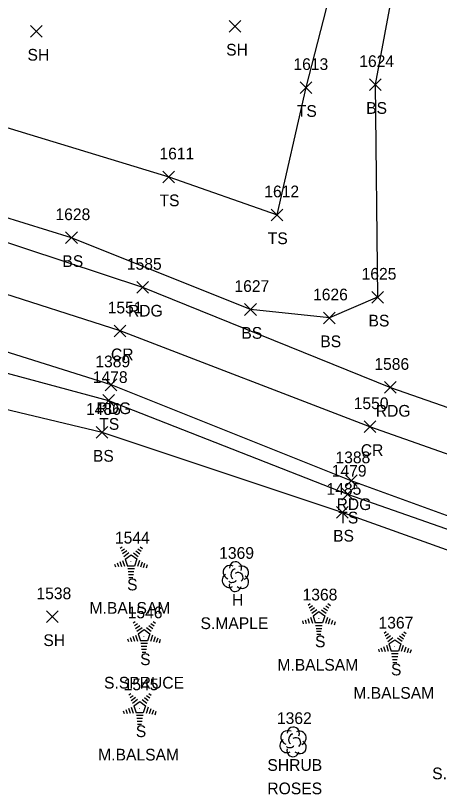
# Model space of a CAD drawing. Extents: x 1609623 to 1616187, y 756677 to 762826.
# Drawn here: x 1610422.7 to 1610495.1, y 761636.2 to 761769.2 of the extents above; entities that cross this region are included whole.
import ezdxf

# ---------------------------------------------------------------- set-up
doc = ezdxf.new("R2010")
doc.units = 0
for name, color, linetype in [('L_A', 7, 'Continuous'), ('L_C', 7, 'Continuous'), ('L_I', 7, 'Continuous'), ('L_TIC', 7, 'Continuous'), ('LELB', 7, 'Continuous'), ('LSH', 7, 'Continuous'), ('LTC', 7, 'Continuous'), ('LTD', 7, 'Continuous'), ('P_A', 7, 'Continuous'), ('P_I', 7, 'Continuous'), ('P_TIC', 7, 'Continuous'), ('PEU', 7, 'Continuous'), ('PRC', 7, 'Continuous')]:
    doc.layers.add(name, color=color, linetype=linetype)

msp = doc.modelspace()

# ---------------------------------------------------------------- linework, layer by layer
at = {"layer": 'L_TIC'}
for points in [[(1610459.18, 761766.38), (1610461.18, 761768.38)], [(1610461.18, 761766.38), (1610459.18, 761768.38)], [(1610425.22, 761765.51), (1610427.22, 761767.51)], [(1610427.22, 761765.51), (1610425.22, 761767.51)], [(1610471.33, 761755.91), (1610473.33, 761757.91)], [(1610473.33, 761755.91), (1610471.33, 761757.91)], [(1610483.15, 761756.42), (1610485.15, 761758.42)], [(1610485.15, 761756.42), (1610483.15, 761758.42)], [(1610447.86, 761740.64), (1610449.86, 761742.64)], [(1610449.86, 761740.64), (1610447.86, 761742.64)], [(1610466.36, 761734.16), (1610468.36, 761736.16)], [(1610468.36, 761734.16), (1610466.36, 761736.16)], [(1610431.23, 761730.26), (1610433.23, 761732.26)], [(1610433.23, 761730.26), (1610431.23, 761732.26)], [(1610483.55, 761720.1), (1610485.55, 761722.1)], [(1610485.55, 761720.1), (1610483.55, 761722.1)], [(1610461.82, 761718), (1610463.82, 761720)], [(1610463.82, 761718), (1610461.82, 761720)], [(1610475.31, 761716.56), (1610477.31, 761718.56)], [(1610477.31, 761716.56), (1610475.31, 761718.56)], [(1610437.56, 761702.45), (1610439.56, 761704.45)], [(1610439.56, 761702.45), (1610437.56, 761704.45)], [(1610436.45, 761697), (1610438.45, 761699)], [(1610438.45, 761697), (1610436.45, 761699)], [(1610478.41, 761686.45), (1610480.41, 761688.45)], [(1610480.41, 761686.45), (1610478.41, 761688.45)], [(1610477.5, 761683.35), (1610479.5, 761685.35)], [(1610479.5, 761683.35), (1610477.5, 761685.35)], [(1610427.93, 761665.51), (1610429.93, 761667.51)], [(1610429.93, 761665.51), (1610427.93, 761667.51)]]:
    msp.add_lwpolyline(points, dxfattribs=at)
at = {"layer": 'LELB'}
for points in [[(1610493.54, 761807.83), (1610484.15, 761757.42), (1610484.55, 761721.1), (1610476.31, 761717.56), (1610462.82, 761719), (1610432.23, 761731.26), (1610407.92, 761738.73), (1610372.44, 761750.91), (1610345.83, 761758.18), (1610340.75, 761759.13), (1610336.33, 761759.9), (1610330.48, 761773.16), (1610321.56, 761783.18), (1610327.07, 761799.85), (1610336.71, 761810.65), (1610352.98, 761818.88), (1610362.46, 761822.54)], [(1610419.05, 761750.7), (1610448.86, 761741.64), (1610467.36, 761735.16), (1610472.33, 761756.91), (1610479.31, 761783.98), (1610481.94, 761811.25), (1610453.47, 761810.17), (1610420.45, 761799.24), (1610406.2, 761793.3), (1610384.28, 761797.2), (1610367.96, 761799.15), (1610357.1, 761783.9)], [(1610257.48, 761736.51), (1610289.65, 761735.58), (1610333.79, 761730.74), (1610390.78, 761716.31), (1610438.56, 761703.45), (1610479.41, 761687.45), (1610522.96, 761672.19), (1610559.63, 761661.11), (1610576.64, 761653.22)], [(1610558.74, 761658.14), (1610522.76, 761668.49), (1610478.5, 761684.35), (1610437.45, 761698), (1610388.31, 761709.71), (1610348.03, 761719.28), (1610335.94, 761728.39)]]:
    msp.add_lwpolyline(points, dxfattribs=at)
at = {"layer": 'LSH'}
msp.add_line((1610470.08, 761645.19), (1610470.08, 761645.19), dxfattribs=at)
msp.add_line((1610470.08, 761645.19), (1610470.08, 761645.19), dxfattribs=at)
msp.add_arc((1610470.13, 761646.63), 1.05, 335.5272, 180.9563, dxfattribs=at)
for centre, major_axis, ratio, start_param, end_param in [((1610469.29, 761645.86), (1.21, -0.51), 0.895232, 1.570796, 4.712389), ((1610471.12, 761645.78), (-1.14, -0.48), 0.949671, 1.570796, 4.712389), ((1610469.87, 761645.65), (-0.208, -0.792), 0.645439, 3.141593, 6.283185), ((1610470.58, 761645.03), (-0.5, 0.667), 0.989748, 3.141593, 6.283185), ((1610469, 761644.48), (0.58, -1.04), 0.959034, 3.141593, 6.283185), ((1610469.62, 761644.44), (-0.625, -0.083), 0.423636, 0, 3.141593), ((1610471.08, 761644.36), (-1.09, 0.79), 0.841452, 1.570796, 4.712389), ((1610470.08, 761643.69), (0.26, 1.06), 0.942809, 1.570796, 4.712389)]:
    msp.add_ellipse(centre, major_axis=major_axis, ratio=ratio, start_param=start_param, end_param=end_param, dxfattribs=at)
at = {"layer": 'LTC'}
for p, q in [((1610440.54, 761678.23), (1610440.9, 761678.48)), ((1610440.75, 761677.76), (1610441.28, 761678.14)), ((1610440.96, 761677.29), (1610441.66, 761677.81)), ((1610443.2, 761677.77), (1610443.88, 761677.28)), ((1610443.57, 761678.12), (1610444.12, 761677.72)), ((1610443.94, 761678.47), (1610444.36, 761678.16)), ((1610441.17, 761676.83), (1610442.05, 761677.47)), ((1610441.39, 761676.37), (1610442.41, 761677.11)), ((1610441.39, 761676.37), (1610441.78, 761675.18)), ((1610442.41, 761677.11), (1610443.4, 761676.38)), ((1610442.83, 761677.42), (1610443.64, 761676.83)), ((1610443.4, 761676.38), (1610443.01, 761675.18)), ((1610439.57, 761675.5), (1610439.73, 761675.04)), ((1610440.03, 761675.72), (1610440.24, 761675.07)), ((1610440.48, 761675.94), (1610440.76, 761675.1)), ((1610440.94, 761676.15), (1610441.27, 761675.14)), ((1610443.01, 761675.18), (1610441.78, 761675.18)), ((1610443.84, 761676.11), (1610443.5, 761675.07)), ((1610444.29, 761675.86), (1610444, 761674.98)), ((1610444.73, 761675.61), (1610444.49, 761674.88)), ((1610445.17, 761675.36), (1610444.99, 761674.79)), ((1610442.97, 761674.68), (1610441.83, 761674.68)), ((1610442.89, 761674.18), (1610441.9, 761674.18)), ((1610442.81, 761673.68), (1610441.97, 761673.68)), ((1610442.72, 761673.18), (1610442.05, 761673.18)), ((1610472.66, 761668.51), (1610473.01, 761668.77)), ((1610472.87, 761668.05), (1610473.4, 761668.43)), ((1610475.68, 761668.4), (1610476.23, 761668.01)), ((1610476.05, 761668.75), (1610476.47, 761668.45)), ((1610473.08, 761667.58), (1610473.78, 761668.09)), ((1610473.29, 761667.12), (1610474.16, 761667.75)), ((1610473.51, 761666.66), (1610474.52, 761667.4)), ((1610474.52, 761667.4), (1610475.52, 761666.67)), ((1610474.94, 761667.71), (1610475.75, 761667.12)), ((1610475.31, 761668.06), (1610475.99, 761667.56)), ((1610442.77, 761665.46), (1610443.12, 761665.72)), ((1610446.17, 761665.7), (1610446.59, 761665.4)), ((1610471.69, 761665.79), (1610471.84, 761665.32)), ((1610472.14, 761666.01), (1610472.36, 761665.36)), ((1610472.6, 761666.23), (1610472.87, 761665.39)), ((1610473.06, 761666.44), (1610473.39, 761665.42)), ((1610473.51, 761666.66), (1610473.9, 761665.47)), ((1610475.52, 761666.67), (1610475.13, 761665.47)), ((1610475.96, 761666.4), (1610475.62, 761665.36)), ((1610476.4, 761666.15), (1610476.11, 761665.26)), ((1610476.85, 761665.9), (1610476.61, 761665.17)), ((1610477.29, 761665.65), (1610477.1, 761665.07)), ((1610442.98, 761665), (1610443.51, 761665.38)), ((1610443.19, 761664.53), (1610443.89, 761665.04)), ((1610443.4, 761664.07), (1610444.28, 761664.7)), ((1610443.62, 761663.61), (1610444.63, 761664.35)), ((1610444.63, 761664.35), (1610445.63, 761663.62)), ((1610445.05, 761664.66), (1610445.86, 761664.07)), ((1610445.43, 761665.01), (1610446.11, 761664.51)), ((1610445.8, 761665.35), (1610446.35, 761664.96)), ((1610475.13, 761665.47), (1610473.9, 761665.47)), ((1610475.09, 761664.97), (1610473.94, 761664.97)), ((1610475.01, 761664.47), (1610474.02, 761664.47)), ((1610442.26, 761662.96), (1610442.47, 761662.31)), ((1610442.71, 761663.18), (1610442.98, 761662.34)), ((1610443.17, 761663.39), (1610443.5, 761662.37)), ((1610443.62, 761663.61), (1610444.01, 761662.42)), ((1610445.63, 761663.62), (1610445.24, 761662.42)), ((1610446.07, 761663.35), (1610445.73, 761662.31)), ((1610446.51, 761663.1), (1610446.23, 761662.21)), ((1610474.92, 761663.97), (1610474.09, 761663.97)), ((1610474.84, 761663.47), (1610474.16, 761663.47)), ((1610485.64, 761663.71), (1610485.99, 761663.97)), ((1610485.85, 761663.24), (1610486.38, 761663.63)), ((1610486.06, 761662.78), (1610486.76, 761663.29)), ((1610488.29, 761663.25), (1610488.97, 761662.76)), ((1610488.66, 761663.6), (1610489.21, 761663.2)), ((1610489.03, 761663.95), (1610489.45, 761663.64)), ((1610441.8, 761662.74), (1610441.95, 761662.27)), ((1610445.24, 761662.42), (1610444.01, 761662.42)), ((1610445.2, 761661.92), (1610444.06, 761661.92)), ((1610446.96, 761662.85), (1610446.72, 761662.12)), ((1610447.4, 761662.6), (1610447.22, 761662.02)), ((1610486.04, 761661.64), (1610486.37, 761660.62)), ((1610486.27, 761662.31), (1610487.14, 761662.95)), ((1610486.49, 761661.86), (1610487.5, 761662.59)), ((1610486.49, 761661.86), (1610486.88, 761660.66)), ((1610487.5, 761662.59), (1610488.5, 761661.87)), ((1610487.92, 761662.9), (1610488.73, 761662.32)), ((1610488.5, 761661.87), (1610488.11, 761660.66)), ((1610445.12, 761661.42), (1610444.13, 761661.42)), ((1610445.03, 761660.92), (1610444.2, 761660.92)), ((1610444.95, 761660.42), (1610444.28, 761660.42)), ((1610484.67, 761660.99), (1610484.82, 761660.52)), ((1610485.12, 761661.2), (1610485.34, 761660.55)), ((1610485.58, 761661.42), (1610485.85, 761660.59)), ((1610488.11, 761660.66), (1610486.88, 761660.66)), ((1610488.94, 761661.6), (1610488.6, 761660.56)), ((1610489.38, 761661.34), (1610489.09, 761660.46)), ((1610489.83, 761661.09), (1610489.59, 761660.37)), ((1610490.27, 761660.84), (1610490.08, 761660.27)), ((1610488.07, 761660.16), (1610486.92, 761660.16)), ((1610487.99, 761659.66), (1610487, 761659.66)), ((1610487.9, 761659.16), (1610487.07, 761659.16)), ((1610487.82, 761658.66), (1610487.14, 761658.66)), ((1610442.03, 761653.17), (1610442.38, 761653.42)), ((1610442.24, 761652.7), (1610442.77, 761653.08)), ((1610442.45, 761652.23), (1610443.15, 761652.75)), ((1610442.66, 761651.77), (1610443.53, 761652.41)), ((1610444.31, 761652.36), (1610445.12, 761651.77)), ((1610444.68, 761652.71), (1610445.36, 761652.22)), ((1610445.05, 761653.06), (1610445.6, 761652.66)), ((1610445.43, 761653.41), (1610445.84, 761653.1)), ((1610442.43, 761651.09), (1610442.76, 761650.07)), ((1610442.88, 761651.31), (1610443.89, 761652.05)), ((1610442.88, 761651.31), (1610443.27, 761650.12)), ((1610443.89, 761652.05), (1610444.89, 761651.32)), ((1610444.89, 761651.32), (1610444.5, 761650.12)), ((1610445.33, 761651.05), (1610444.99, 761650.01)), ((1610441.06, 761650.44), (1610441.21, 761649.98)), ((1610441.52, 761650.66), (1610441.73, 761650.01)), ((1610441.97, 761650.88), (1610442.24, 761650.04)), ((1610444.5, 761650.12), (1610443.27, 761650.12)), ((1610445.77, 761650.8), (1610445.48, 761649.92)), ((1610446.22, 761650.55), (1610445.98, 761649.82)), ((1610446.66, 761650.3), (1610446.47, 761649.73)), ((1610444.46, 761649.62), (1610443.32, 761649.62)), ((1610444.38, 761649.12), (1610443.39, 761649.12)), ((1610444.29, 761648.62), (1610443.46, 761648.62)), ((1610444.21, 761648.12), (1610443.53, 761648.12))]:
    msp.add_line(p, q, dxfattribs=at)
at = {"layer": 'LTD'}
msp.add_line((1610460.22, 761673.41), (1610460.22, 761673.41), dxfattribs=at)
msp.add_line((1610460.22, 761673.41), (1610460.22, 761673.41), dxfattribs=at)
msp.add_arc((1610460.27, 761674.84), 1.05, 335.5272, 180.9563, dxfattribs=at)
for centre, major_axis, ratio, start_param, end_param in [((1610459.43, 761674.07), (1.21, -0.51), 0.895232, 1.570796, 4.712389), ((1610461.26, 761673.99), (-1.14, -0.48), 0.949671, 1.570796, 4.712389), ((1610459.14, 761672.7), (0.58, -1.04), 0.959034, 3.141593, 6.283185), ((1610460.01, 761673.86), (-0.208, -0.792), 0.645439, 3.141593, 6.283185), ((1610460.72, 761673.24), (-0.5, 0.667), 0.989748, 3.141593, 6.283185), ((1610459.76, 761672.66), (-0.625, -0.083), 0.423636, 0, 3.141593), ((1610461.22, 761672.57), (-1.09, 0.79), 0.841452, 1.570796, 4.712389), ((1610460.22, 761671.91), (0.26, 1.06), 0.942809, 1.570796, 4.712389)]:
    msp.add_ellipse(centre, major_axis=major_axis, ratio=ratio, start_param=start_param, end_param=end_param, dxfattribs=at)
at = {"layer": 'P_TIC'}
for points in [[(1610443.38, 761721.79), (1610445.38, 761723.79)], [(1610445.38, 761721.79), (1610443.38, 761723.79)], [(1610439.53, 761714.33), (1610441.53, 761716.33)], [(1610441.53, 761714.33), (1610439.53, 761716.33)], [(1610438, 761705.13), (1610440, 761707.13)], [(1610440, 761705.13), (1610438, 761707.13)], [(1610485.74, 761704.69), (1610487.74, 761706.69)], [(1610487.74, 761704.69), (1610485.74, 761706.69)], [(1610482.24, 761697.98), (1610484.24, 761699.98)], [(1610484.24, 761697.98), (1610482.24, 761699.98)], [(1610479.04, 761688.74), (1610481.04, 761690.74)], [(1610481.04, 761688.74), (1610479.04, 761690.74)]]:
    msp.add_lwpolyline(points, dxfattribs=at)
at = {"layer": 'PEU'}
for points in [[(1610292.65, 761756.84), (1610337.52, 761752.5), (1610397.05, 761738.41), (1610444.38, 761722.79), (1610486.74, 761705.69), (1610529.9, 761690.62)], [(1610523.28, 761673.99), (1610480.04, 761689.74), (1610439, 761706.13), (1610392.08, 761720.87), (1610334.48, 761734.06), (1610288.63, 761739.63), (1610237.75, 761740.33), (1610189.36, 761741.54), (1610151.21, 761743.29), (1610095.63, 761747.13), (1610049.42, 761749.13), (1609994.68, 761742.82), (1609943, 761732.03), (1609889.61, 761718.43), (1609806.51, 761697.21)]]:
    msp.add_lwpolyline(points, dxfattribs=at)
at = {"layer": 'PRC'}
msp.add_lwpolyline([(1610601.8, 761670.75), (1610582.15, 761672.46), (1610527.05, 761683.5), (1610483.24, 761698.98), (1610440.53, 761715.33), (1610395.01, 761729.94), (1610335.18, 761743.5), (1610288.69, 761747.54), (1610237.99, 761746.29), (1610189.61, 761747.71), (1610150.7, 761750.53), (1610096.59, 761755.33), (1610048.73, 761756.09), (1609993.41, 761750.2), (1609941.26, 761738.94), (1609887.62, 761725.82), (1609805.01, 761705.08)], dxfattribs=at)

# ---------------------------------------------------------------- texts
at = {"layer": 'L_A'}
for s, p in [('SH', (1610458.66, 761762.38)), ('SH', (1610424.71, 761761.51)), ('TS', (1610470.74, 761751.91)), ('BS', (1610482.59, 761752.42)), ('TS', (1610447.27, 761736.64)), ('TS', (1610465.77, 761730.16)), ('BS', (1610430.67, 761726.26)), ('BS', (1610482.99, 761716.1)), ('BS', (1610461.26, 761714)), ('BS', (1610474.75, 761712.56)), ('TS', (1610436.97, 761698.45)), ('BS', (1610435.89, 761693)), ('TS', (1610477.82, 761682.45)), ('BS', (1610476.94, 761679.35)), ('S', (1610441.73, 761671.02)), ('H', (1610459.65, 761668.41)), ('SH', (1610427.42, 761661.51)), ('S', (1610473.85, 761661.3)), ('S', (1610443.96, 761658.25)), ('S', (1610486.83, 761656.5)), ('S', (1610443.22, 761645.96)), ('SHRUB', (1610465.71, 761640.19))]:
    msp.add_text(s, height=2, dxfattribs=at).set_placement(p)
at = {"layer": 'L_C'}
for s, p in [('M.BALSAM', (1610435.31, 761667.02)), ('S.MAPLE', (1610454.28, 761664.41)), ('M.BALSAM', (1610467.42, 761657.3)), ('S.SPRUCE', (1610437.79, 761654.25)), ('M.BALSAM', (1610480.4, 761652.5)), ('M.BALSAM', (1610436.79, 761641.96)), ('S.MAPLE', (1610493.87, 761638.75)), ('ROSES', (1610465.7, 761636.19))]:
    msp.add_text(s, height=2, dxfattribs=at).set_placement(p)
at = {"layer": 'L_I'}
for s, p in [('1613', (1610470.16, 761759.91)), ('1624', (1610481.41, 761760.42)), ('1611', (1610447.26, 761744.64)), ('1612', (1610465.18, 761738.16)), ('1628', (1610429.49, 761734.26)), ('1625', (1610481.81, 761724.1)), ('1627', (1610460.08, 761722)), ('1626', (1610473.51, 761720.56)), ('1478', (1610435.87, 761706.45)), ('1486', (1610434.71, 761701)), ('1479', (1610476.71, 761690.45)), ('1485', (1610475.81, 761687.35)), ('1544', (1610439.65, 761679.02)), ('1369', (1610457.47, 761676.41)), ('1538', (1610426.24, 761669.51)), ('1368', (1610471.72, 761669.3)), ('1546', (1610441.83, 761666.25)), ('1367', (1610484.7, 761664.5)), ('1545', (1610441.14, 761653.96)), ('1362', (1610467.34, 761648.19))]:
    msp.add_text(s, height=2, dxfattribs=at).set_placement(p)
at = {"layer": 'LTC'}
for p in [(1610442.29, 761676.12), (1610474.4, 761666.41), (1610444.52, 761663.36), (1610487.38, 761661.6), (1610443.77, 761651.06)]:
    msp.add_text('.', height=1.04, rotation=270, dxfattribs=at).set_placement(p)
at = {"layer": 'P_A'}
for s, p in [('RDG', (1610441.87, 761717.79)), ('CR', (1610438.97, 761710.33)), ('RDG', (1610436.49, 761701.13)), ('RDG', (1610484.23, 761700.69)), ('CR', (1610481.67, 761693.98)), ('RDG', (1610477.53, 761684.74))]:
    msp.add_text(s, height=2, dxfattribs=at).set_placement(p)
at = {"layer": 'P_I'}
for s, p in [('1585', (1610441.69, 761725.79)), ('1551', (1610438.41, 761718.33)), ('1389', (1610436.3, 761709.13)), ('1586', (1610483.99, 761708.69)), ('1550', (1610480.46, 761701.98)), ('1388', (1610477.35, 761692.74))]:
    msp.add_text(s, height=2, dxfattribs=at).set_placement(p)

doc.saveas('drawing.dxf')
